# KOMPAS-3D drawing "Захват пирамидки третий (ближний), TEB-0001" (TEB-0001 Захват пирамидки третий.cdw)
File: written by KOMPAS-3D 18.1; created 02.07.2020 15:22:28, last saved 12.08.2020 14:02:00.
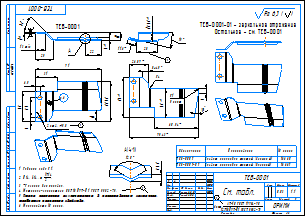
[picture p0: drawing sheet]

Sheet 1: A3, landscape

Document properties: Полное имя файла: F:\Чертежи\ЧАЙ\TSUBAKI\TEB\TEB-0001 и TEB-0001-01\TEB-0001 Захват пирамидки третий.cdw; Организация: ООО "ОРИМИ"; Знак неуказанной шероховатости: 4; Параметр неуказанной шероховатости: Ra 6,3; Масса: 0.0283916; Наименование: См. табл

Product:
- Part/product: Захват пирамидки третий (ближний)  | designation TEB-0001
    Материал: Лист$d1 ГОСТ 19904-90;12Х18Н9Т-Н1 ГОСТ 7350-77$ (density 7900 kg/m3)
    Масса: 0.0283916
    source file: TEB-0001 Захват пирамидки третий.cdw
- Part/product: Захват пирамидки третий (дальний)  | designation TEB-0001-01
    Материал: Лист$d1 ГОСТ 19904-90;12Х18Н9Т-Н1 ГОСТ 7350-77$ (density 7900 kg/m3)
    Масса: 0.0283916
- Part/product: Развёртка  | designation TEB-0001-02
    Материал: Лист$d1 ГОСТ 19904-90;12Х18Н9Т-Н1 ГОСТ 7350-77$ (density 7900 kg/m3)
    Масса: 0.028285
    source file: TEB-0001 Захват пирамидки третий.cdw

Title block, sheet 1: Наименование: См. табл.; designation: TEB-0001; Материал: Лист АТ-1,0 ГОСТ 19904-90 12Х18Н9Т-Н1 ГОСТ 5582-75; Масса: 0,03; Количество листов документа: 1; organisation: ОРИМИ; Форматы листов документа: A3; stored path: F:\Чертежи\ЧАЙ\TSUBAKI\TEB\TEB-0001 и TEB-0001-01\Захват пирамидки третий.cdw; Разработал: Баличев Д.С.; Проверил: Киселёв С.Д.; Разработал, date: 02.07.20

Views: Вид 1, Проекционный вид 2, Проекционный вид 3, Вид 4, Спереди, Вид 5, Развертка, Проекционный вид 6, Вид 7, Вид 8, Выносной элемент 9, Выносной элемент А, Выносной элемент
Referenced files in F:\Чертежи\ЧАЙ\TSUBAKI\TEB\TEB-0001 и TEB-0001-01\: Захват пирамидки третий.m3d, TEB-0001 Захват пирамидки третий.m3d
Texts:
  min
  Главный
  JS12
  Слой 1
  TEB-0001 - 01
  Остальное - см.  TEB-0001
  ID номер
  Захват пирамидки третий (ближний)
  TEB-0001-01
  Захват пирамидки третий (дальний)
  TEB-0001-02
  Развёртка
  TEB-0001 - 01
  TEB-0001 - 02
  Стиль таблицы исполнений
  Ra 6,3
  Ra 6,3 ( )
  Зам.
  ОГМ01184
Dimensions and other numbers on the sheet: 11; 13; 4; 25; 1; 22; 27; 91; 6; 6,5; 55,75; 16; 31; 42; 2 отв.; 5,8; 12,45; 28; 11,6; 16660; 16661; 95,43; 56; 60,54; 40; 26,89; 8; 7; 5 мест; 120; 2,45; 1:1; 0,03; 02.07.20; 12.08.20; 01; 02

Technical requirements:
  Радиусы гиба R1.
  *Размеры для справок.
  Материал-заменитель 08Х18Н9Т-Н1 ГОСТ 5582-75.
  Сталь применять исключительно в нагартованном состоянии,
  требуются пружинные свойства.
  Маркировать ID номер.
